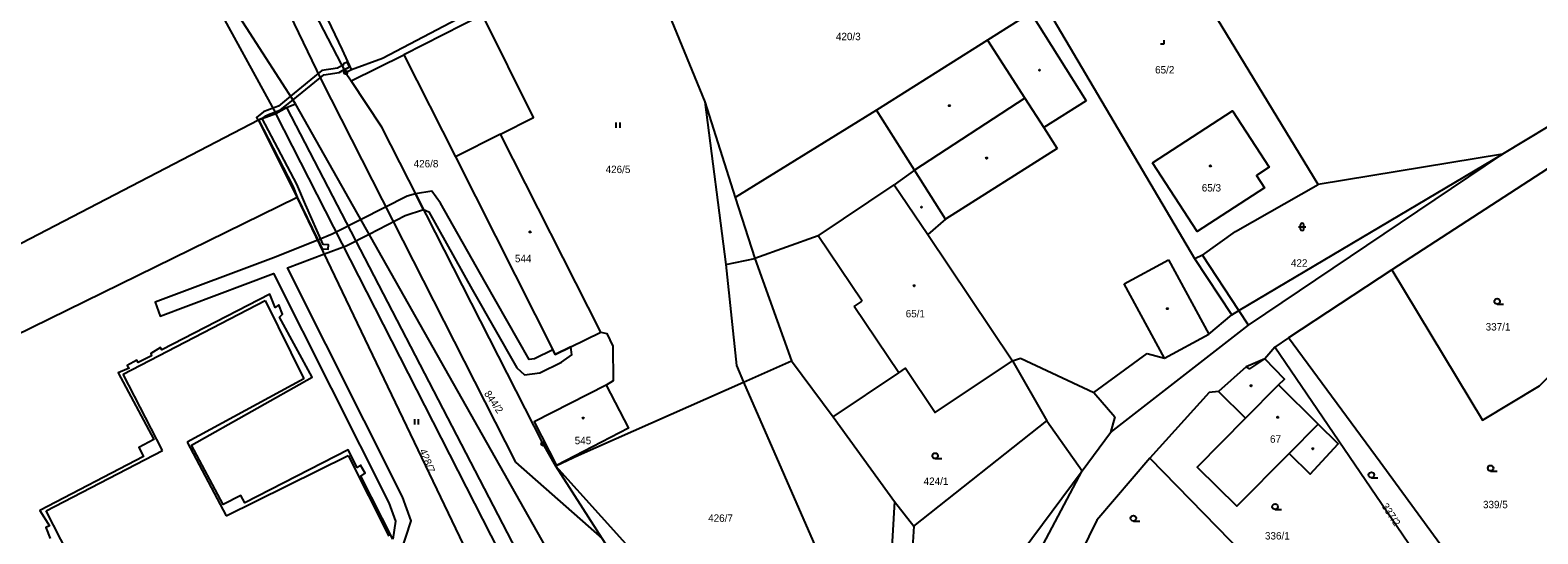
# Model space of a CAD drawing. Extents: x -745926 to -742978, y -968282 to -965689.
# Drawn here: x -745176.7 to -744972.9, y -966781 to -966712.9 of the extents above; entities that cross this region are included whole.
import ezdxf

# ---------------------------------------------------------------- set-up
doc = ezdxf.new("R2010")
doc.units = 0
for name, color, linetype in [('Hranice parcel', 7, 'Continuous'), ('Parcelní čísla', 7, 'Continuous'), ('Vnitřní kresba', 7, 'Continuous'), ('Věcná břemena k části', 7, 'Continuous'), ('Značky bodu BP', 7, 'Continuous'), ('Značky budov', 7, 'Continuous'), ('Značky kultur', 7, 'Continuous')]:
    doc.layers.add(name, color=color, linetype=linetype)

msp = doc.modelspace()

# ---------------------------------------------------------------- linework, layer by layer
at = {"layer": 'Hranice parcel'}
for p, q in [((-745153.75, -966680.76), (-745134.06, -966718.61)), ((-745002.62, -966733.75), (-745023.44, -966699.46)), ((-744946.43, -966710.72), (-744977.68, -966729.66)), ((-745133.31, -966719.75), (-745126.19, -966716.22)), ((-745134.06, -966718.61), (-745133.31, -966719.75)), ((-745098.15, -966798.38), (-745140.83, -966722.83)), ((-745232.51, -966770.07), (-745145.82, -966725.01)), ((-745140.59, -966735.47), (-745145.82, -966725.01)), ((-744964.4, -966726.95), (-744992.64, -966745.31)), ((-745012.02, -966752.75), (-744977.68, -966729.66)), ((-744977.68, -966729.66), (-745002.62, -966733.75)), ((-745115.39, -966788.09), (-745140.59, -966735.47)), ((-744992.64, -966745.31), (-745006.6, -966754.49)), ((-745006.6, -966754.49), (-745008.46, -966755.75)), ((-745073.79, -966757.57), (-745068.18, -966765.16)), ((-745008.46, -966755.75), (-745009.84, -966757.33)), ((-744988.3, -966785.4), (-745008.46, -966755.75)), ((-745068.18, -966765.16), (-745059.86, -966776.62)), ((-745057.26, -966779.94), (-745039.27, -966765.68)), ((-745039.27, -966765.68), (-745034.52, -966772.46)), ((-745105.66, -966771.81), (-745105.56, -966771.75)), ((-745025.37, -966770.73), (-745000.7, -966796)), ((-745059.86, -966776.62), (-745057.26, -966779.94))]:
    msp.add_line(p, q, dxfattribs=at)
for points in [[(-745140.83, -966722.83), (-745147.45, -966712.59), (-745163.29, -966688.08)], [(-745134.06, -966718.61), (-745133.29, -966718.19), (-745129.07, -966716.66), (-745096.03, -966699.27)], [(-745099.55, -966753.7), (-745113.13, -966726.94), (-745108.67, -966724.69), (-745115.57, -966710.82), (-745126.19, -966716.22)], [(-745090.38, -966710.74), (-745085.52, -966722.6), (-745081.39, -966735.5)], [(-745039.46, -966709.62), (-745041.45, -966710.54), (-745047.3, -966714.23), (-745062.3, -966723.69), (-745081.39, -966735.5)], [(-745018.23, -966743.31), (-745019.27, -966743.78), (-745039.46, -966709.62)], [(-745126.19, -966716.22), (-745119.23, -966730.02), (-745105.74, -966756.73), (-745099.55, -966753.7)], [(-745105.66, -966771.81), (-745107.37, -966768.82), (-745129.19, -966726.01), (-745133.31, -966719.75)], [(-745145.82, -966725.01), (-745143.49, -966724.15), (-745142.04, -966723.37), (-745140.83, -966722.83)], [(-745025.02, -966730.82), (-745014.21, -966723.79), (-745009.25, -966731.41), (-745010.95, -966732.52), (-745009.85, -966734.2), (-745018.96, -966740.13), (-745025.02, -966730.82)], [(-745018.23, -966743.31), (-745013.78, -966740.09), (-745002.62, -966733.75)], [(-745081.39, -966735.5), (-745078.74, -966743.76), (-745073.79, -966757.57)], [(-745012.02, -966752.75), (-745013.31, -966750.78), (-745018.23, -966743.31)], [(-744992.64, -966745.31), (-744980.4, -966765.62), (-744972.7, -966760.99), (-744967.7, -966755.9), (-744961.83, -966752.65)], [(-745127.7, -966781.7), (-745132, -966773.2), (-745131.42, -966772.76), (-745132.06, -966771.7), (-745132.5, -966772), (-745133.7, -966769.6), (-745147.7, -966776.8), (-745148.21, -966775.77), (-745150.61, -966777.02), (-745154.9, -966769), (-745138.6, -966759.8), (-745143, -966751.7), (-745142.6, -966751.3), (-745143.1, -966750), (-745143.6, -966750.4), (-745144.3, -966748.6), (-745158.9, -966756.1), (-745159.1, -966755.8), (-745160.4, -966756.6), (-745160.3, -966756.9), (-745162.1, -966757.8), (-745162.3, -966757.5), (-745163.6, -966758.2), (-745163.3, -966758.6), (-745164.8, -966759.2), (-745160, -966768.2), (-745162, -966769.3), (-745161.4, -966770.5), (-745175.4, -966777.8), (-745174.1, -966779.9), (-745174.6, -966780.1), (-745174, -966781.6)], [(-745099.55, -966753.7), (-745098.75, -966753.88), (-745097.96, -966755.61), (-745097.88, -966760.28), (-745098.84, -966760.87)], [(-745034.52, -966772.46), (-745030.69, -966767.27), (-745012.02, -966752.75)], [(-744988.3, -966785.4), (-744985.3, -966783.5), (-744994.24, -966771.28), (-745006.6, -966754.49)], [(-745105.56, -966771.75), (-745102.6, -966770.33), (-745080.27, -966760.47), (-745073.79, -966757.57)], [(-745068.18, -966765.16), (-745059.31, -966759.19), (-745058.4, -966758.57), (-745054.37, -966764.59), (-745043.94, -966757.61), (-745039.27, -966765.68)], [(-745016.06, -966761.73), (-745012.41, -966765.34), (-745018.95, -966771.94), (-745013.61, -966777.23), (-745006.55, -966770.11), (-745003.71, -966772.93), (-744999.9, -966768.83), (-745002.61, -966766.14), (-745007.96, -966760.84), (-745007.18, -966760.06), (-745009.84, -966757.33)], [(-745009.84, -966757.33), (-745012.33, -966758.42), (-745016.06, -966761.73)], [(-745098.84, -966760.87), (-745108.58, -966765.83), (-745105.56, -966771.75)], [(-745098.84, -966760.87), (-745095.82, -966766.71), (-745105.56, -966771.75)], [(-745016.06, -966761.73), (-745017.34, -966761.88), (-745025.37, -966770.73)], [(-745089.36, -966797.13), (-745099.37, -966781.59), (-745105.66, -966771.81)], [(-745083.66, -966793.89), (-745087.11, -966792.36), (-745105.66, -966771.81)], [(-745025.37, -966770.73), (-745032.52, -966779.12), (-745038.02, -966790.33), (-745040.33, -966801.98)], [(-745043.69, -966795.22), (-745044.66, -966791.59), (-745034.52, -966772.46)], [(-745059.86, -966776.62), (-745060.37, -966785.1), (-745054.46, -966792.69), (-745047.89, -966799.85), (-745045.46, -966802.72)], [(-745057.26, -966779.94), (-745057.47, -966783.53), (-745051.39, -966790.32), (-745046.34, -966793.53), (-745043.69, -966795.22)]]:
    msp.add_lwpolyline(points, dxfattribs=at)
at = {"layer": 'Vnitřní kresba'}
for p, q in [((-745134.5, -966715.55), (-745151.72, -966679.2)), ((-745155.45, -966682.06), (-745137.43, -966719.51)), ((-745163.29, -966688.08), (-745143.49, -966724.15)), ((-745041.45, -966710.54), (-745033.95, -966722.44)), ((-745047.3, -966714.23), (-745042.26, -966722.09)), ((-745133.29, -966718.19), (-745134.5, -966715.55)), ((-745137.43, -966719.51), (-745111.1, -966771.27)), ((-745085.52, -966722.6), (-745082.67, -966744.59)), ((-745042.26, -966722.09), (-745057.19, -966731.8)), ((-745042.26, -966722.09), (-745039.69, -966726.05)), ((-745033.95, -966722.44), (-745039.69, -966726.05)), ((-745111.82, -966786.22), (-745143.49, -966724.15)), ((-745142.04, -966723.37), (-745107.02, -966790.83)), ((-745057.19, -966731.8), (-745062.3, -966723.69)), ((-745113.13, -966726.94), (-745119.23, -966730.02)), ((-745039.69, -966726.05), (-745037.88, -966728.91)), ((-745037.88, -966728.91), (-745052.99, -966738.44)), ((-745013.31, -966750.78), (-744977.68, -966729.66)), ((-745057.19, -966731.8), (-745059.9, -966733.8)), ((-745052.99, -966738.44), (-745057.19, -966731.8)), ((-745070.17, -966740.68), (-745059.9, -966733.8)), ((-745059.9, -966733.8), (-745055.39, -966740.53)), ((-745228.69, -966778.6), (-745140.59, -966735.47)), ((-745052.99, -966738.44), (-745055.39, -966740.53)), ((-745070.17, -966740.68), (-745078.74, -966743.76)), ((-745064.25, -966749.51), (-745070.17, -966740.68)), ((-745055.39, -966740.53), (-745043.94, -966757.61)), ((-745082.67, -966744.59), (-745078.74, -966743.76)), ((-745082.67, -966744.59), (-745081.24, -966758.24)), ((-745028.81, -966747.17), (-745022.84, -966743.94)), ((-745022.84, -966743.94), (-745017.39, -966754)), ((-745014.28, -966751.36), (-745019.27, -966743.78)), ((-745023.36, -966757.23), (-745028.81, -966747.17)), ((-745164.15, -966759.38), (-745144.95, -966749.44)), ((-745144.95, -966749.44), (-745139.7, -966760)), ((-745065.32, -966750.23), (-745064.25, -966749.51)), ((-745059.31, -966759.19), (-745065.32, -966750.23)), ((-745017.39, -966754), (-745014.28, -966751.36)), ((-745014.28, -966751.36), (-745013.31, -966750.78)), ((-745023.36, -966757.23), (-745017.39, -966754)), ((-745043.94, -966757.61), (-745042.85, -966757.24)), ((-745042.85, -966757.24), (-745032.94, -966761.88)), ((-745032.94, -966761.88), (-745025.7, -966756.6)), ((-745025.7, -966756.6), (-745023.36, -966757.23)), ((-745011.85, -966758.67), (-745009.84, -966757.33)), ((-745158.81, -966769.71), (-745164.15, -966759.38)), ((-745081.24, -966758.24), (-745080.27, -966760.47)), ((-745012.33, -966758.42), (-745011.85, -966758.67)), ((-745139.7, -966760), (-745155.5, -966768.6)), ((-745080.27, -966760.47), (-745069.24, -966785.7)), ((-745012.41, -966765.34), (-745007.96, -966760.84)), ((-745032.94, -966761.88), (-745030.1, -966765.16)), ((-745030.1, -966765.16), (-745030.69, -966767.27)), ((-745006.55, -966770.11), (-745002.61, -966766.14)), ((-745174.56, -966777.86), (-745158.81, -966769.71)), ((-745155.5, -966768.6), (-745150.2, -966778.53)), ((-745150.2, -966778.53), (-745133.7, -966770.4)), ((-745133.7, -966770.4), (-745128.2, -966781.3)), ((-745111.1, -966771.27), (-745099.37, -966781.59)), ((-745042.62, -966783.36), (-745034.52, -966772.46)), ((-745168.68, -966789.23), (-745174.56, -966777.86))]:
    msp.add_line(p, q, dxfattribs=at)
at = {"layer": 'Věcná břemena k části'}
for points in [[(-745137.27, -966718.35), (-745141.5, -966721.8), (-745141.17, -966722.3), (-745137.01, -966718.92), (-745134.94, -966718.61), (-745134.27, -966718.21), (-745134.54, -966717.68), (-745135.14, -966718.03)], [(-745134.29, -966717.53), (-745134.54, -966717.68), (-745134.27, -966718.21), (-745134.01, -966718.07), (-745133.98, -966718.13), (-745133.52, -966717.87), (-745133.87, -966717.22), (-745134.33, -966717.45)], [(-745141.17, -966722.3), (-745141.5, -966721.8), (-745143.15, -966723.15), (-745143.64, -966723.34), (-745144.69, -966723.75), (-745145.15, -966723.94), (-745146.1, -966724.69), (-745145.91, -966725.06), (-745145.82, -966725.01), (-745145.35, -966724.83), (-745144.85, -966724.46), (-745144.47, -966724.31), (-745143.42, -966723.9), (-745142.85, -966723.67)], [(-745137.25, -966742.45), (-745136.4, -966742.5), (-745136.36, -966741.9), (-745137.11, -966741.85), (-745139.5, -966736.46), (-745140.66, -966733.72), (-745145.35, -966724.83), (-745145.82, -966725.01), (-745141.2, -966733.98), (-745140.59, -966735.47)], [(-745124.6, -966735.02), (-745123.52, -966737.13), (-745122.82, -966737.44), (-745116.96, -966747.94), (-745110.92, -966758.53), (-745109.9, -966759.47), (-745107.81, -966759.21), (-745104.9, -966757.75), (-745103.48, -966756.8), (-745103.64, -966755.7), (-745105.74, -966756.73), (-745106.05, -966756.12), (-745108.54, -966757.34), (-745109.25, -966757.41), (-745115.22, -966746.94), (-745121.22, -966736.26), (-745122.39, -966734.66)]]:
    msp.add_lwpolyline(points, close=True, dxfattribs=at)
msp.add_lwpolyline([(-745126.66, -966783.62), (-745125.21, -966779.21), (-745126.39, -966775.97), (-745141.94, -966745.03), (-745136.92, -966743.14), (-745134, -966742.05), (-745130.88, -966740.45), (-745126.02, -966737.95), (-745123.52, -966737.13), (-745124.6, -966735.02), (-745125.74, -966735.33), (-745131.98, -966738.5), (-745135.9, -966740.49), (-745137.82, -966741.26), (-745143.81, -966743.65), (-745159.8, -966749.66), (-745159.11, -966751.53), (-745143.8, -966745.78), (-745128.23, -966776.77), (-745127.33, -966779.24), (-745127.7, -966781.7)], dxfattribs=at)
at = {"layer": 'Značky bodu BP'}
for centre, radius in [((-745134.06, -966718.61), 0.25), ((-745134.06, -966718.61), 0.0152), ((-745107.37, -966768.82), 0.25), ((-745107.37, -966768.82), 0.0152)]:
    msp.add_circle(centre, radius, dxfattribs=at)
at = {"layer": 'Značky budov'}
for centre in [(-745040.28, -966718.3), (-745052.45, -966723.1), (-745047.42, -966730.19), (-745017.18, -966731.25), (-745056.22, -966736.82), (-745109.13, -966740.16), (-745057.22, -966747.44), (-745022.98, -966750.54), (-745011.68, -966760.95), (-745101.95, -966765.33), (-745008.08, -966765.21), (-745003.33, -966769.47)]:
    msp.add_circle(centre, 0.0875, dxfattribs=at)
at = {"layer": 'Značky kultur'}
for p, q in [((-745023.91, -966714.75), (-745023.41, -966714.75)), ((-745023.41, -966714.75), (-745023.41, -966714.25)), ((-745097.48, -966726.11), (-745097.48, -966725.36)), ((-745096.97, -966726.11), (-745096.97, -966725.36)), ((-745005.04, -966739.24), (-745005.04, -966739.74)), ((-745004.54, -966739.74), (-745004.54, -966739.24)), ((-745005.29, -966739.49), (-745004.29, -966739.49)), ((-744978.42, -966749.94), (-744977.54, -966749.94)), ((-745124.69, -966766.21), (-745124.69, -966765.46)), ((-745124.19, -966766.21), (-745124.19, -966765.46)), ((-745054.37, -966770.81), (-745053.49, -966770.81)), ((-744995.41, -966773.39), (-744994.53, -966773.39)), ((-744979.3, -966772.48), (-744978.42, -966772.48)), ((-745008.43, -966777.69), (-745007.55, -966777.69)), ((-745027.59, -966779.25), (-745026.71, -966779.25))]:
    msp.add_line(p, q, dxfattribs=at)
for centre in [(-744978.42, -966749.56), (-745054.37, -966770.43), (-744979.3, -966772.1), (-744995.41, -966773.01), (-745008.43, -966777.31), (-745027.59, -966778.87)]:
    msp.add_circle(centre, 0.375, dxfattribs=at)
for centre, start, end in [((-745004.79, -966739.24), 0, 180), ((-745004.79, -966739.74), 180, 359.9879)]:
    msp.add_arc(centre, 0.25, start, end, dxfattribs=at)

# ---------------------------------------------------------------- texts
at = {"layer": 'Parcelní čísla'}
for s, p in [('420/3', (-745067.79, -966714.25)), ('65/2', (-745024.65, -966718.75)), ('426/8', (-745124.87, -966731.44)), ('426/5', (-745098.92, -966732.21)), ('65/3', (-745018.34, -966734.7)), ('544', (-745111.18, -966744.26)), ('422', (-745006.29, -966744.86)), ('65/1', (-745058.36, -966751.71)), ('337/1', (-744979.97, -966753.49)), ('545', (-745103.1, -966768.86)), ('67', (-745009.12, -966768.66)), ('424/1', (-745055.94, -966774.36)), ('339/5', (-744980.33, -966777.51)), ('426/7', (-745085.06, -966779.35)), ('336/1', (-745009.8, -966781.74))]:
    msp.add_text(s, height=1, dxfattribs=at).set_placement(p)
for s, rotation, p in [('844/2', 304, (-745115.39, -966762.03)), ('428/7', 292, (-745124.12, -966769.73)), ('337/2', 303, (-744994.08, -966777.23))]:
    msp.add_text(s, height=1, rotation=rotation, dxfattribs=at).set_placement(p)

doc.saveas('drawing.dxf')
